Omron CX-Programmer project NeuesProjekt (CX-Programmer 7.21)

# PLC NeueSPS2: CJ1G-H CPU42
I/O table (CPU CJ1G-CPU42H): rack 0 slot 0 CJ1W-INT01

## Global symbols (name address type ; comment)
D1000 CHANNEL  ; MV Input 0,00...100,00
D1001 CHANNEL  ; Full Stroke
D1002 CHANNEL  ; Pulse Zeit
D1003 CHANNEL  ; Pausen Zeit
D1004 CHANNEL  ; Totband in %
D1005 CHANNEL  ; Upper Limit in %
D1006 CHANNEL  ; Lower Limit in %
D1011 CHANNEL  ; Interne Ventillaufzeit 0,00...100,00s
D1021 CHANNEL  ; positive letzte Laufzeit
D1023 CHANNEL  ; negatve letzte Laufzeit
D104 CHANNEL  ; Sollaufzeit aus macro
D1040 CHANNEL  ; Differenz soll Ist
D1041 CHANNEL  ; Pulse Zeit x 10
D30000 CHANNEL  ; UpperLimit%in Real
D30002 CHANNEL  ; LowerLimit% in Real
D30004 CHANNEL  ; U Limit in Lzeit 1/100s Real
D30006 CHANNEL  ; L limit in Lzeit1/100s Real
D30010 CHANNEL  ; FullStrokeReal
D30012 CHANNEL  ; MVInput Real
D30016 CHANNEL  ; FullStrokeReal in 1/100s
D30018 CHANNEL  ; 0,01% = Zeit(1/100)
D30020 CHANNEL  ; SollLaufzeitReal1/100s
W100.02 BOOL  ; Ventil zu
W100.03 BOOL  ; Ventil auf
W101.01 BOOL  ; Ventil an oberer Grenze
W101.02 BOOL  ; Ventil an unterer Grenze
W10.00 BOOL  ; Obere Enlage NC
W10.01 BOOL  ; Untere Endlage NC
W10.10 BOOL  ; Ausgang Ventil Auf
W10.11 BOOL  ; Ausgang Ventil Zu
test1 Drei_Punkt_Schritt
test2 Drei_Punkt_Schritt

## Program NeuesProgramm1 (cyclic task 0)

### Section Sektion1

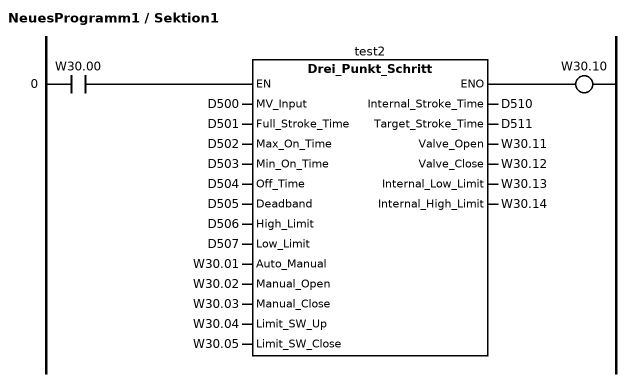
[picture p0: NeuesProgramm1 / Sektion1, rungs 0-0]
; rung 0
LD W30.00
CALL test2 : Drei_Punkt_Schritt (MV_Input := D500, Full_Stroke_Time := D501, Max_On_Time := D502, Min_On_Time := D503, Off_Time := D504, Deadband := D505, High_Limit := D506, Low_Limit := D507, Auto_Manual := W30.01, Manual_Open := W30.02, Manual_Close := W30.03, Limit_SW_Up := W30.04, Limit_SW_Close := W30.05, Internal_Stroke_Time => D510, Target_Stroke_Time => D511, Valve_Open => W30.11, Valve_Close => W30.12, Internal_Low_Limit => W30.13, Internal_High_Limit => W30.14)
OUT W30.10

### Section END
; rung 0
END(001)

## Function block Drei_Punkt_Schritt
VAR_INPUT
  MV_Input : INT;  (* 0,00%...100,00% *)
  Full_Stroke_Time : INT;  (* 10,0...300,0 s *)
  Max_On_Time : INT;  (* 0,1...10,0 Max_On_Time>Min_On_Time *)
  Min_On_Time : INT;  (* 0,1...10,0s Min_On_Time<Max_On_Time *)
  Off_Time : INT;  (* 0,1...10,0s *)
  Deadband : INT;  (* 0,00...100,00% *)
  High_Limit : INT;  (* 0,00...100,00% High_Limit>Low_Limit *)
  Low_Limit : INT;  (* 0,00...100,00% Low_Limit<High_Limit *)
  Auto_Manual : BOOL;  (* 0=Manual 1=Auto *)
  Manual_Open : BOOL;
  Manual_Close : BOOL;
  Limit_SW_Up : BOOL;  (* 1=No Limit *)
  Limit_SW_Close : BOOL;  (* 1=No Limit *)
END_VAR
VAR_OUTPUT
  Internal_Stroke_Time : INT;  (* 0,00...300,00s *)
  Target_Stroke_Time : INT;  (* 0,00...300,00s *)
  Valve_Open : BOOL;
  Valve_Close : BOOL;
  Internal_Low_Limit : BOOL;
  Internal_High_Limit : BOOL;
END_VAR
VAR
  Open_calculate : TIMER;
  ClosePause : TIMER;
  OpenPause : TIMER;
  Close_calculate : TIMER;
  PulseClose : TIMER;
  PulseOpen : TIMER;
  Startup : TIMER;
  IT1 : TIMER;
  IT2 : TIMER;
  ZE10 : REAL;
  Cal_PulseTimeR : REAL;  (* Calculated Pulse Time in Real *)
  ZE11 : REAL;
  FST_MemoryR : REAL;
  Internal_Stroke_TimeR : REAL;
  ZE12 : REAL;
  ZE13 : REAL;
  DifferencePercentR : REAL;
  DifferenceR : REAL;
  FullStrokeReal : REAL;
  FullStrokeReal1_100s : REAL;
  High_LimitR : REAL;
  ZE5 : REAL;
  ZE4 : REAL;
  ZE3 : REAL;
  Percent_to_time : REAL;  (* 0,01%-> in time 1/100s *)
  MV_InputReal : REAL;
  MV_In_Stroketime : REAL;
  Low_LimitR : REAL;
  MaxOnTimeR : REAL;
  Cal_P_Tx10 : DINT;
  LastOpenTime : INT;
  LastCloseTime : INT;
  ZE2 : INT;
  ZE1 : INT;
  Cal_PulseTime : INT;
  HighStrokeTime : INT;  (* Upper Limit Valve in Stroke Time 1/100s *)
  DeadLowL : INT;
  DeadUpL : INT;
  Difference : INT;  (* Difference in 1/100s *)
  MV_Memory : INT;
  LowStrokeTime : INT;  (* Lower Limit Valve in Stroke Time 1/100s *)
  FST_Memory : INT;
  opening : BOOL;
  TowardsClose : BOOL;
  Closing : BOOL;
  TowardsOpen : BOOL;
  Valve_Lower_Limit : BOOL;
  Valve_Upper_Limit : BOOL;
  M1 : BOOL;
  M2 : BOOL;
  TB1 : BOOL;
  TB2 : BOOL;
END_VAR

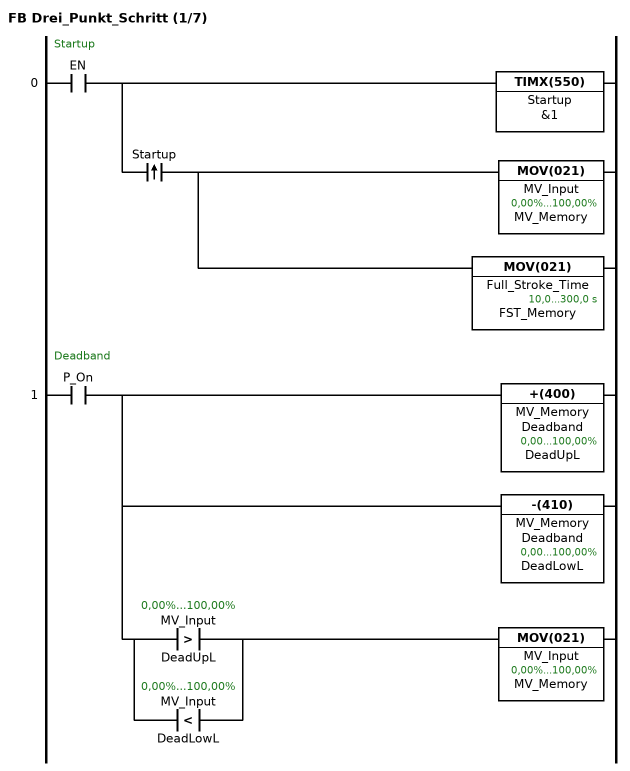
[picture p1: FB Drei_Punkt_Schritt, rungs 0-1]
; rung 0: Startup
LD EN
TIMX(550) Startup &1
@AND Startup
MOV(021) MV_Input MV_Memory  ; 0,00%...100,00%
MOV(021) Full_Stroke_Time FST_Memory  ; 10,0...300,0 s
; rung 1: Deadband
LD P_On
+(400) MV_Memory Deadband DeadUpL  ; 0,00...100,00%
-(410) MV_Memory Deadband DeadLowL  ; 0,00...100,00%
LD>(320) MV_Input DeadUpL  ; 0,00%...100,00%
OR<(310) MV_Input DeadLowL  ; 0,00%...100,00%
ANDLD
MOV(021) MV_Input MV_Memory  ; 0,00%...100,00%

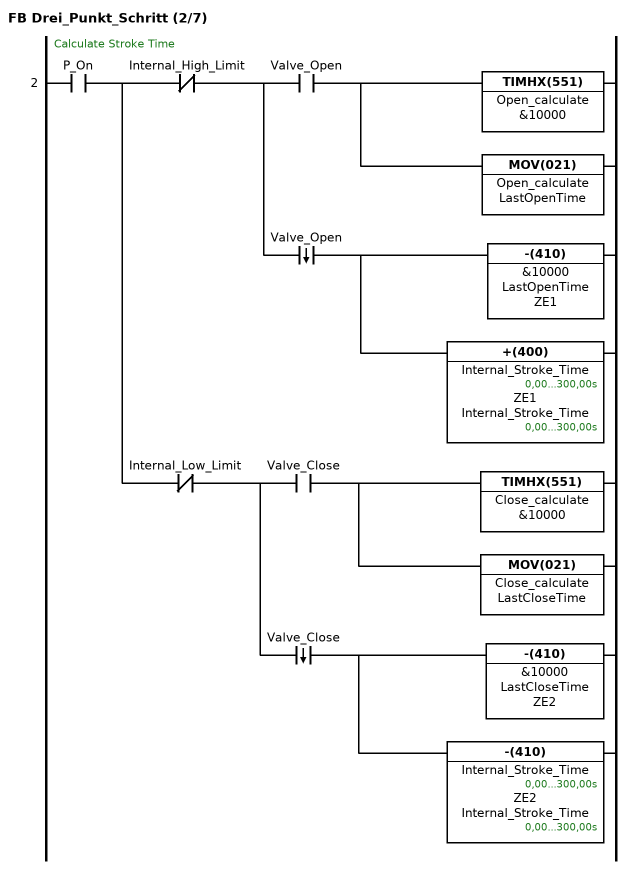
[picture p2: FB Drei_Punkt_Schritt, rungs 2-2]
; rung 2: Calculate Stroke Time
LD P_On
OUT TR0
ANDNOT Internal_High_Limit
OUT TR1
AND Valve_Open
TIMHX(551) Open_calculate &10000
MOV(021) Open_calculate LastOpenTime
LD TR1
%AND Valve_Open
-(410) &10000 LastOpenTime ZE1
+(400) Internal_Stroke_Time ZE1 Internal_Stroke_Time  ; 0,00...300,00s
LD TR0
ANDNOT Internal_Low_Limit
OUT TR2
AND Valve_Close
TIMHX(551) Close_calculate &10000
MOV(021) Close_calculate LastCloseTime
LD TR2
%AND Valve_Close
-(410) &10000 LastCloseTime ZE2
-(410) Internal_Stroke_Time ZE2 Internal_Stroke_Time  ; 0,00...300,00s

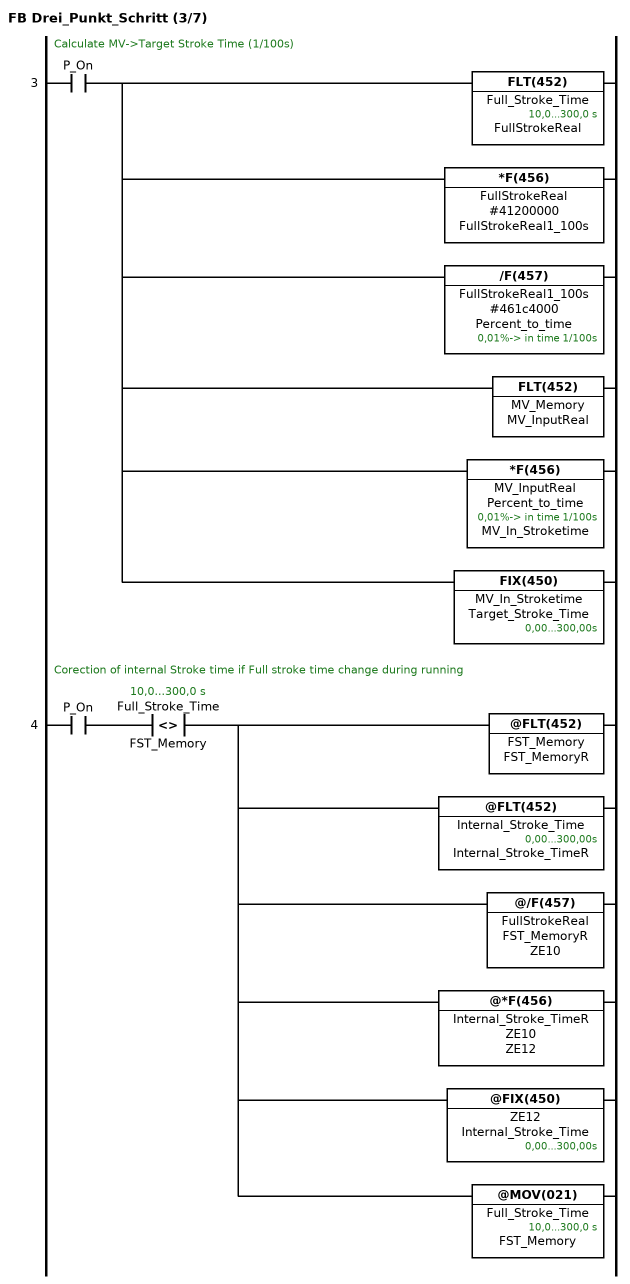
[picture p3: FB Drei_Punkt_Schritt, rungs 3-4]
; rung 3: Calculate MV->Target Stroke Time (1/100s)
LD P_On
FLT(452) Full_Stroke_Time FullStrokeReal  ; 10,0...300,0 s
*F(456) FullStrokeReal #41200000 FullStrokeReal1_100s
/F(457) FullStrokeReal1_100s #461c4000 Percent_to_time  ; 0,01%-> in time 1/100s
FLT(452) MV_Memory MV_InputReal
*F(456) MV_InputReal Percent_to_time MV_In_Stroketime  ; 0,01%-> in time 1/100s
FIX(450) MV_In_Stroketime Target_Stroke_Time  ; 0,00...300,00s
; rung 4: Corection of internal Stroke time if Full stroke time change during running
LD P_On
AND<>(305) Full_Stroke_Time FST_Memory  ; 10,0...300,0 s
@FLT(452) FST_Memory FST_MemoryR
@FLT(452) Internal_Stroke_Time Internal_Stroke_TimeR  ; 0,00...300,00s
@/F(457) FullStrokeReal FST_MemoryR ZE10
@*F(456) Internal_Stroke_TimeR ZE10 ZE12
@FIX(450) ZE12 Internal_Stroke_Time  ; 0,00...300,00s
@MOV(021) Full_Stroke_Time FST_Memory  ; 10,0...300,0 s

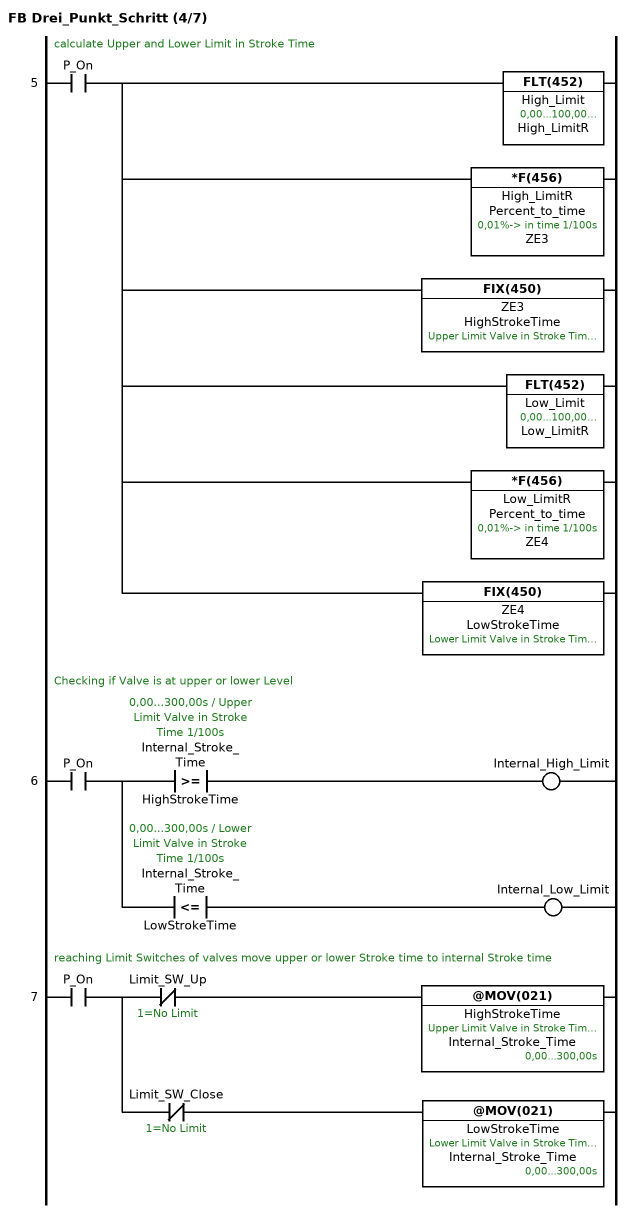
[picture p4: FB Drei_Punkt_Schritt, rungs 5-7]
; rung 5: calculate Upper and Lower Limit in Stroke Time
LD P_On
FLT(452) High_Limit High_LimitR  ; 0,00...100,00% High_Limit>Low_Limit
*F(456) High_LimitR Percent_to_time ZE3  ; 0,01%-> in time 1/100s
FIX(450) ZE3 HighStrokeTime  ; Upper Limit Valve in Stroke Time 1/100s
FLT(452) Low_Limit Low_LimitR  ; 0,00...100,00% Low_Limit<High_Limit
*F(456) Low_LimitR Percent_to_time ZE4  ; 0,01%-> in time 1/100s
FIX(450) ZE4 LowStrokeTime  ; Lower Limit Valve in Stroke Time 1/100s
; rung 6: Checking if Valve is at upper or lower Level
LD P_On
OUT TR0
AND>=(325) Internal_Stroke_Time HighStrokeTime  ; 0,00...300,00s, Upper Limit Valve in Stroke Time 1/100s
OUT Internal_High_Limit
LD TR0
AND<=(315) Internal_Stroke_Time LowStrokeTime  ; 0,00...300,00s, Lower Limit Valve in Stroke Time 1/100s
OUT Internal_Low_Limit
; rung 7: reaching Limit Switches of valves move upper or lower Stroke time to internal Stroke time
LD P_On
OUT TR0
ANDNOT Limit_SW_Up  ; 1=No Limit
@MOV(021) HighStrokeTime Internal_Stroke_Time  ; Upper Limit Valve in Stroke Time 1/100s, 0,00...300,00s
LD TR0
ANDNOT Limit_SW_Close  ; 1=No Limit
@MOV(021) LowStrokeTime Internal_Stroke_Time  ; Lower Limit Valve in Stroke Time 1/100s, 0,00...300,00s

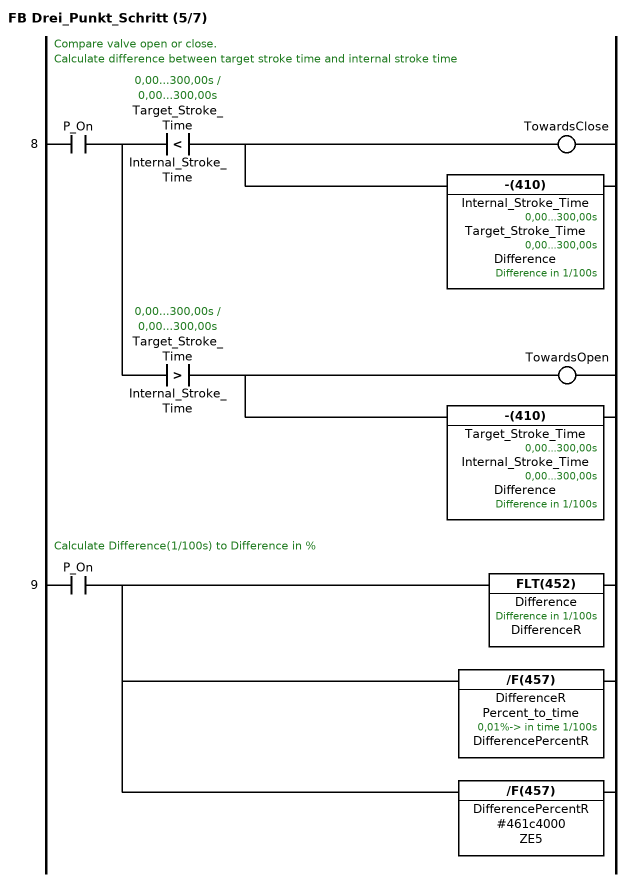
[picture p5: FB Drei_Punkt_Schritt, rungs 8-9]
; rung 8: Compare valve open or close. / Calculate difference between target stroke time and internal stroke time
LD P_On
OUT TR0
AND<(310) Target_Stroke_Time Internal_Stroke_Time  ; 0,00...300,00s
OUT TowardsClose
-(410) Internal_Stroke_Time Target_Stroke_Time Difference  ; 0,00...300,00s, Difference in 1/100s
LD TR0
AND>(320) Target_Stroke_Time Internal_Stroke_Time  ; 0,00...300,00s
OUT TowardsOpen
-(410) Target_Stroke_Time Internal_Stroke_Time Difference  ; 0,00...300,00s, Difference in 1/100s
; rung 9: Calculate Difference(1/100s) to Difference in %
LD P_On
FLT(452) Difference DifferenceR  ; Difference in 1/100s
/F(457) DifferenceR Percent_to_time DifferencePercentR  ; 0,01%-> in time 1/100s
/F(457) DifferencePercentR #461c4000 ZE5

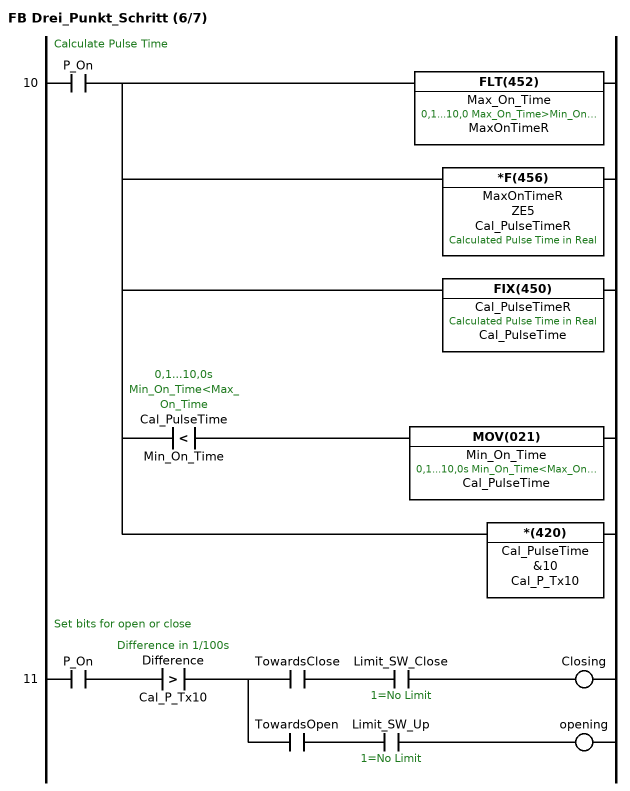
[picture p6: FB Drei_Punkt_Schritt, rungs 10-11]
; rung 10: Calculate Pulse Time
LD P_On
OUT TR0
FLT(452) Max_On_Time MaxOnTimeR  ; 0,1...10,0 Max_On_Time>Min_On_Time
*F(456) MaxOnTimeR ZE5 Cal_PulseTimeR  ; Calculated Pulse Time in Real
FIX(450) Cal_PulseTimeR Cal_PulseTime  ; Calculated Pulse Time in Real
AND<(310) Cal_PulseTime Min_On_Time  ; 0,1...10,0s Min_On_Time<Max_On_Time
MOV(021) Min_On_Time Cal_PulseTime  ; 0,1...10,0s Min_On_Time<Max_On_Time
LD TR0
*(420) Cal_PulseTime &10 Cal_P_Tx10
; rung 11: Set bits for open or close
LD P_On
AND>(320) Difference Cal_P_Tx10  ; Difference in 1/100s
OUT TR0
AND TowardsClose
AND Limit_SW_Close  ; 1=No Limit
OUT Closing
LD TR0
AND TowardsOpen
AND Limit_SW_Up  ; 1=No Limit
OUT opening

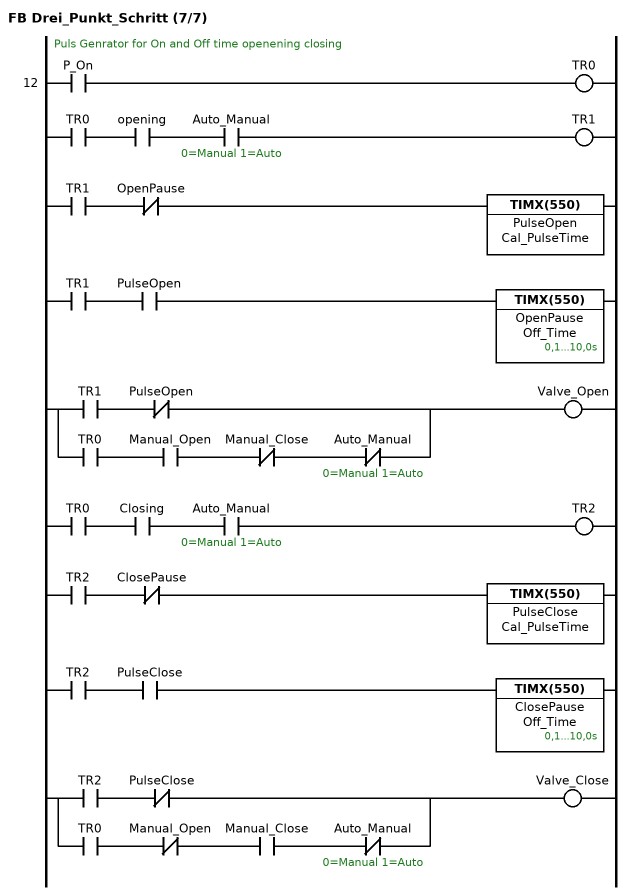
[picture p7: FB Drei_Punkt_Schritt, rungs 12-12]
; rung 12: Puls Genrator for On and Off time openening closing
LD P_On
OUT TR0
LD TR0
AND opening
AND Auto_Manual  ; 0=Manual 1=Auto
OUT TR1
LD TR1
ANDNOT OpenPause
TIMX(550) PulseOpen Cal_PulseTime
LD TR1
AND PulseOpen
TIMX(550) OpenPause Off_Time  ; 0,1...10,0s
LD TR1
ANDNOT PulseOpen
LD TR0
AND Manual_Open
ANDNOT Manual_Close
ANDNOT Auto_Manual  ; 0=Manual 1=Auto
ORLD
OUT Valve_Open
LD TR0
AND Closing
AND Auto_Manual  ; 0=Manual 1=Auto
OUT TR2
LD TR2
ANDNOT ClosePause
TIMX(550) PulseClose Cal_PulseTime
LD TR2
AND PulseClose
TIMX(550) ClosePause Off_Time  ; 0,1...10,0s
LD TR2
ANDNOT PulseClose
LD TR0
ANDNOT Manual_Open
AND Manual_Close
ANDNOT Auto_Manual  ; 0=Manual 1=Auto
ORLD
OUT Valve_Close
